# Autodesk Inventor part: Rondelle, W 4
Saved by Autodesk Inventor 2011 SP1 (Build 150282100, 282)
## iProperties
Created: 2010-12
Part Number: Rondelle, W 4
Document SubType Name: Modeling
Designer: eric
Density: 1 g/cm^3
Author: eric
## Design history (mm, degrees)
feature "Base1"
node "Solide1"
node "Corps solides"
node "Corps surfaciques"
